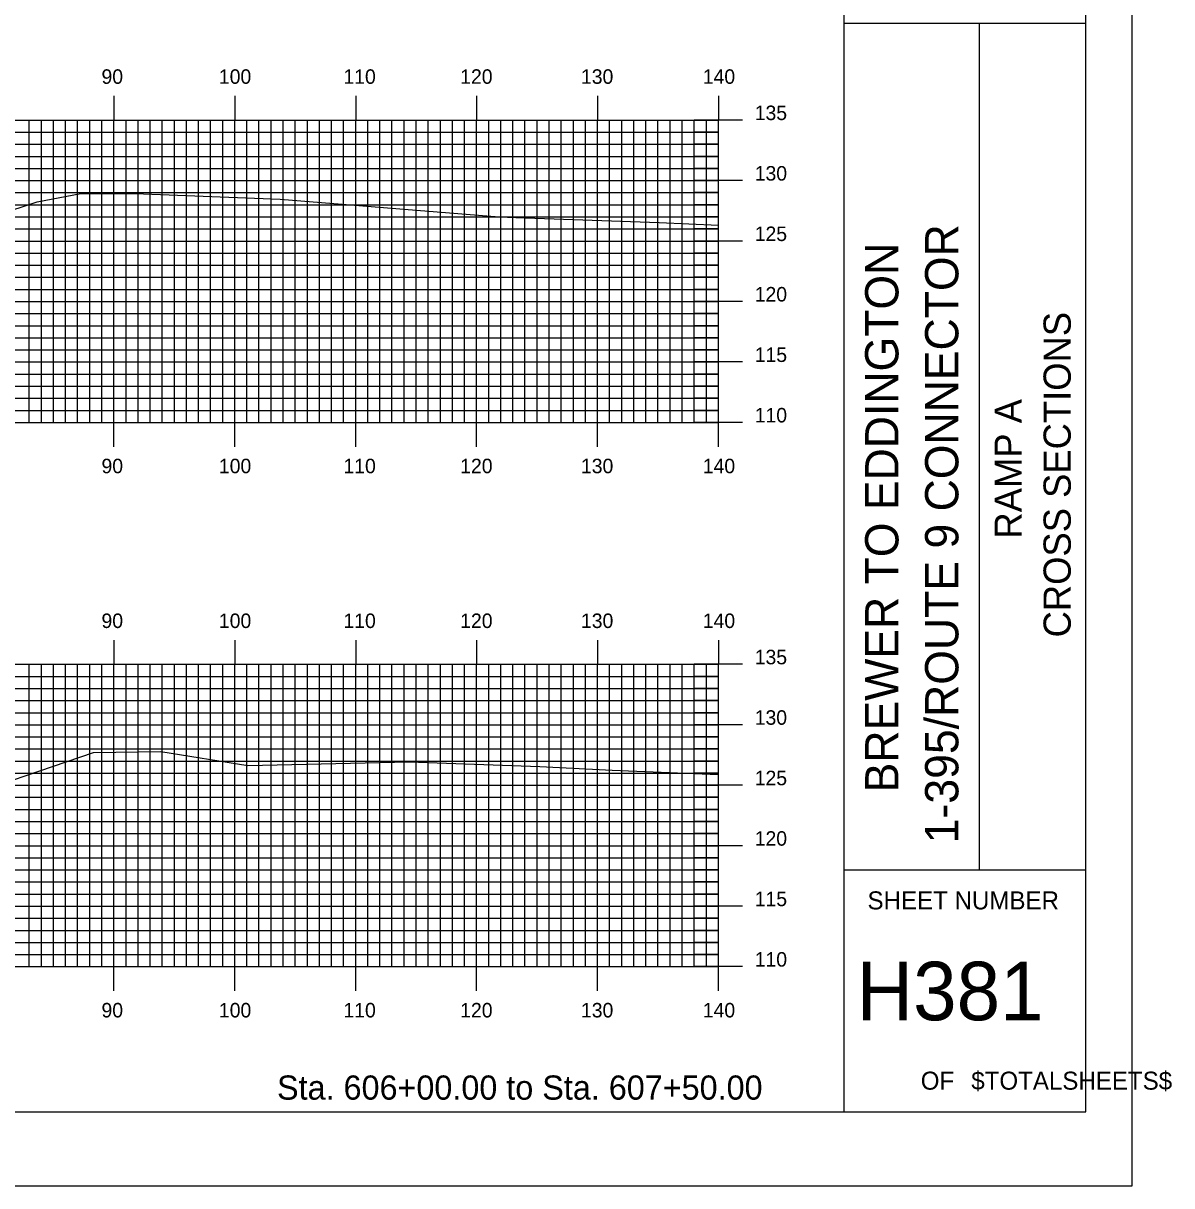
# Model space of a CAD drawing. Extents: x 842569 to 842912, y 363538 to 363758.
# Drawn here: x 842816.9 to 842911.9, y 363537.6 to 363633.7 of the extents above; entities that cross this region are included whole.
import ezdxf

# ---------------------------------------------------------------- set-up
doc = ezdxf.new("R2010")
doc.units = 0
for name, color, linetype in [('BORDER', 7, 'Continuous'), ('H_V ANNOTATION', 7, 'Continuous'), ('MAJOR', 7, 'Continuous'), ('MINOR', 7, 'Continuous'), ('PLOT BOUNDARY', 7, 'Continuous'), ('S_Roadway_Centerline', 7, 'Continuous')]:
    doc.layers.add(name, color=color, linetype=linetype)

msp = doc.modelspace()

# ---------------------------------------------------------------- linework, layer by layer
at = {"layer": 'BORDER'}
for p, q in [((842884.798, 363543.721), (842884.798, 363753.721)), ((842884.798, 363633.727), (842904.798, 363633.727)), ((842895.98, 363563.727), (842895.98, 363633.727)), ((842884.798, 363563.727), (842904.798, 363563.727))]:
    msp.add_line(p, q, dxfattribs=at)
msp.add_lwpolyline([(842584.798, 363543.721), (842904.798, 363543.721), (842904.798, 363753.721), (842584.798, 363753.721)], close=True, dxfattribs=at)
at = {"layer": 'MAJOR'}
for p, q in [((842824.398, 363627.725), (842824.398, 363625.721)), ((842834.398, 363627.725), (842834.398, 363625.721)), ((842844.398, 363627.725), (842844.398, 363625.721)), ((842854.398, 363627.725), (842854.398, 363625.721)), ((842864.398, 363627.725), (842864.398, 363625.721)), ((842874.398, 363627.725), (842874.398, 363625.721)), ((842594.398, 363625.721), (842874.398, 363625.721)), ((842594.398, 363625.721), (842874.398, 363625.721)), ((842824.398, 363600.721), (842824.398, 363625.721)), ((842834.398, 363600.721), (842834.398, 363625.721)), ((842844.398, 363600.721), (842844.398, 363625.721)), ((842854.398, 363600.721), (842854.398, 363625.721)), ((842864.398, 363600.721), (842864.398, 363625.721)), ((842876.402, 363625.721), (842872.394, 363625.721)), ((842874.398, 363600.721), (842874.398, 363625.721)), ((842874.398, 363600.721), (842874.398, 363625.721)), ((842594.398, 363620.721), (842874.398, 363620.721)), ((842876.402, 363620.721), (842872.394, 363620.721)), ((842594.398, 363615.721), (842874.398, 363615.721)), ((842876.402, 363615.721), (842872.394, 363615.721)), ((842594.398, 363610.721), (842874.398, 363610.721)), ((842876.402, 363610.721), (842872.394, 363610.721)), ((842594.398, 363605.721), (842874.398, 363605.721)), ((842876.402, 363605.721), (842872.394, 363605.721)), ((842594.398, 363600.721), (842874.398, 363600.721)), ((842594.398, 363600.721), (842874.398, 363600.721)), ((842824.398, 363598.717), (842824.398, 363600.721)), ((842834.398, 363598.717), (842834.398, 363600.721)), ((842844.398, 363598.717), (842844.398, 363600.721)), ((842854.398, 363598.717), (842854.398, 363600.721)), ((842864.398, 363598.717), (842864.398, 363600.721)), ((842876.402, 363600.721), (842872.394, 363600.721)), ((842874.398, 363598.717), (842874.398, 363600.721)), ((842824.398, 363582.725), (842824.398, 363580.721)), ((842834.398, 363582.725), (842834.398, 363580.721)), ((842844.398, 363582.725), (842844.398, 363580.721)), ((842854.398, 363582.725), (842854.398, 363580.721)), ((842864.398, 363582.725), (842864.398, 363580.721)), ((842874.398, 363582.725), (842874.398, 363580.721)), ((842594.398, 363580.721), (842874.398, 363580.721)), ((842594.398, 363580.721), (842874.398, 363580.721)), ((842824.398, 363555.721), (842824.398, 363580.721)), ((842834.398, 363555.721), (842834.398, 363580.721)), ((842844.398, 363555.721), (842844.398, 363580.721)), ((842854.398, 363555.721), (842854.398, 363580.721)), ((842864.398, 363555.721), (842864.398, 363580.721)), ((842876.402, 363580.721), (842872.394, 363580.721)), ((842874.398, 363555.721), (842874.398, 363580.721)), ((842874.398, 363555.721), (842874.398, 363580.721)), ((842594.398, 363575.721), (842874.398, 363575.721)), ((842876.402, 363575.721), (842872.394, 363575.721)), ((842594.398, 363570.721), (842874.398, 363570.721)), ((842876.402, 363570.721), (842872.394, 363570.721)), ((842594.398, 363565.721), (842874.398, 363565.721)), ((842876.402, 363565.721), (842872.394, 363565.721)), ((842594.398, 363560.721), (842874.398, 363560.721)), ((842876.402, 363560.721), (842872.394, 363560.721)), ((842594.398, 363555.721), (842874.398, 363555.721)), ((842594.398, 363555.721), (842874.398, 363555.721)), ((842824.398, 363553.717), (842824.398, 363555.721)), ((842834.398, 363553.717), (842834.398, 363555.721)), ((842844.398, 363553.717), (842844.398, 363555.721)), ((842854.398, 363553.717), (842854.398, 363555.721)), ((842864.398, 363553.717), (842864.398, 363555.721)), ((842876.402, 363555.721), (842872.394, 363555.721)), ((842874.398, 363553.717), (842874.398, 363555.721))]:
    msp.add_line(p, q, dxfattribs=at)
at = {"layer": 'MINOR'}
for p, q in [((842817.398, 363600.721), (842817.398, 363625.721)), ((842818.398, 363600.721), (842818.398, 363625.721)), ((842819.398, 363600.721), (842819.398, 363625.721)), ((842820.398, 363600.721), (842820.398, 363625.721)), ((842821.398, 363600.721), (842821.398, 363625.721)), ((842822.398, 363600.721), (842822.398, 363625.721)), ((842823.398, 363600.721), (842823.398, 363625.721)), ((842825.398, 363600.721), (842825.398, 363625.721)), ((842826.398, 363600.721), (842826.398, 363625.721)), ((842827.398, 363600.721), (842827.398, 363625.721)), ((842828.398, 363600.721), (842828.398, 363625.721)), ((842829.398, 363600.721), (842829.398, 363625.721)), ((842830.398, 363600.721), (842830.398, 363625.721)), ((842831.398, 363600.721), (842831.398, 363625.721)), ((842832.398, 363600.721), (842832.398, 363625.721)), ((842833.398, 363600.721), (842833.398, 363625.721)), ((842835.398, 363600.721), (842835.398, 363625.721)), ((842836.398, 363600.721), (842836.398, 363625.721)), ((842837.398, 363600.721), (842837.398, 363625.721)), ((842838.398, 363600.721), (842838.398, 363625.721)), ((842839.398, 363600.721), (842839.398, 363625.721)), ((842840.398, 363600.721), (842840.398, 363625.721)), ((842841.398, 363600.721), (842841.398, 363625.721)), ((842842.398, 363600.721), (842842.398, 363625.721)), ((842843.398, 363600.721), (842843.398, 363625.721)), ((842845.398, 363600.721), (842845.398, 363625.721)), ((842846.398, 363600.721), (842846.398, 363625.721)), ((842847.398, 363600.721), (842847.398, 363625.721)), ((842848.398, 363600.721), (842848.398, 363625.721)), ((842849.398, 363600.721), (842849.398, 363625.721)), ((842850.398, 363600.721), (842850.398, 363625.721)), ((842851.398, 363600.721), (842851.398, 363625.721)), ((842852.398, 363600.721), (842852.398, 363625.721)), ((842853.398, 363600.721), (842853.398, 363625.721)), ((842855.398, 363600.721), (842855.398, 363625.721)), ((842856.398, 363600.721), (842856.398, 363625.721)), ((842857.398, 363600.721), (842857.398, 363625.721)), ((842858.398, 363600.721), (842858.398, 363625.721)), ((842859.398, 363600.721), (842859.398, 363625.721)), ((842860.398, 363600.721), (842860.398, 363625.721)), ((842861.398, 363600.721), (842861.398, 363625.721)), ((842862.398, 363600.721), (842862.398, 363625.721)), ((842863.398, 363600.721), (842863.398, 363625.721)), ((842865.398, 363600.721), (842865.398, 363625.721)), ((842866.398, 363600.721), (842866.398, 363625.721)), ((842867.398, 363600.721), (842867.398, 363625.721)), ((842868.398, 363600.721), (842868.398, 363625.721)), ((842869.398, 363600.721), (842869.398, 363625.721)), ((842870.398, 363600.721), (842870.398, 363625.721)), ((842871.398, 363600.721), (842871.398, 363625.721)), ((842872.398, 363600.721), (842872.398, 363625.721)), ((842873.398, 363600.721), (842873.398, 363625.721)), ((842594.398, 363624.721), (842874.398, 363624.721)), ((842874.398, 363624.721), (842872.394, 363624.721)), ((842594.398, 363623.721), (842874.398, 363623.721)), ((842874.398, 363623.721), (842872.394, 363623.721)), ((842594.398, 363622.721), (842874.398, 363622.721)), ((842874.398, 363622.721), (842872.394, 363622.721)), ((842594.398, 363621.721), (842874.398, 363621.721)), ((842874.398, 363621.721), (842872.394, 363621.721)), ((842594.398, 363619.721), (842874.398, 363619.721)), ((842874.398, 363619.721), (842872.394, 363619.721)), ((842594.398, 363618.721), (842874.398, 363618.721)), ((842874.398, 363618.721), (842872.394, 363618.721)), ((842594.398, 363617.721), (842874.398, 363617.721)), ((842874.398, 363617.721), (842872.394, 363617.721)), ((842594.398, 363616.721), (842874.398, 363616.721)), ((842874.398, 363616.721), (842872.394, 363616.721)), ((842594.398, 363614.721), (842874.398, 363614.721)), ((842874.398, 363614.721), (842872.394, 363614.721)), ((842594.398, 363613.721), (842874.398, 363613.721)), ((842874.398, 363613.721), (842872.394, 363613.721)), ((842594.398, 363612.721), (842874.398, 363612.721)), ((842874.398, 363612.721), (842872.394, 363612.721)), ((842594.398, 363611.721), (842874.398, 363611.721)), ((842874.398, 363611.721), (842872.394, 363611.721)), ((842594.398, 363609.721), (842874.398, 363609.721)), ((842874.398, 363609.721), (842872.394, 363609.721)), ((842594.398, 363608.721), (842874.398, 363608.721)), ((842874.398, 363608.721), (842872.394, 363608.721)), ((842594.398, 363607.721), (842874.398, 363607.721)), ((842874.398, 363607.721), (842872.394, 363607.721)), ((842594.398, 363606.721), (842874.398, 363606.721)), ((842874.398, 363606.721), (842872.394, 363606.721)), ((842594.398, 363604.721), (842874.398, 363604.721)), ((842874.398, 363604.721), (842872.394, 363604.721)), ((842594.398, 363603.721), (842874.398, 363603.721)), ((842874.398, 363603.721), (842872.394, 363603.721)), ((842594.398, 363602.721), (842874.398, 363602.721)), ((842874.398, 363602.721), (842872.394, 363602.721)), ((842594.398, 363601.721), (842874.398, 363601.721)), ((842874.398, 363601.721), (842872.394, 363601.721)), ((842817.398, 363555.721), (842817.398, 363580.721)), ((842818.398, 363555.721), (842818.398, 363580.721)), ((842819.398, 363555.721), (842819.398, 363580.721)), ((842820.398, 363555.721), (842820.398, 363580.721)), ((842821.398, 363555.721), (842821.398, 363580.721)), ((842822.398, 363555.721), (842822.398, 363580.721)), ((842823.398, 363555.721), (842823.398, 363580.721)), ((842825.398, 363555.721), (842825.398, 363580.721)), ((842826.398, 363555.721), (842826.398, 363580.721)), ((842827.398, 363555.721), (842827.398, 363580.721)), ((842828.398, 363555.721), (842828.398, 363580.721)), ((842829.398, 363555.721), (842829.398, 363580.721)), ((842830.398, 363555.721), (842830.398, 363580.721)), ((842831.398, 363555.721), (842831.398, 363580.721)), ((842832.398, 363555.721), (842832.398, 363580.721)), ((842833.398, 363555.721), (842833.398, 363580.721)), ((842835.398, 363555.721), (842835.398, 363580.721)), ((842836.398, 363555.721), (842836.398, 363580.721)), ((842837.398, 363555.721), (842837.398, 363580.721)), ((842838.398, 363555.721), (842838.398, 363580.721)), ((842839.398, 363555.721), (842839.398, 363580.721)), ((842840.398, 363555.721), (842840.398, 363580.721)), ((842841.398, 363555.721), (842841.398, 363580.721)), ((842842.398, 363555.721), (842842.398, 363580.721)), ((842843.398, 363555.721), (842843.398, 363580.721)), ((842845.398, 363555.721), (842845.398, 363580.721)), ((842846.398, 363555.721), (842846.398, 363580.721)), ((842847.398, 363555.721), (842847.398, 363580.721)), ((842848.398, 363555.721), (842848.398, 363580.721)), ((842849.398, 363555.721), (842849.398, 363580.721)), ((842850.398, 363555.721), (842850.398, 363580.721)), ((842851.398, 363555.721), (842851.398, 363580.721)), ((842852.398, 363555.721), (842852.398, 363580.721)), ((842853.398, 363555.721), (842853.398, 363580.721)), ((842855.398, 363555.721), (842855.398, 363580.721)), ((842856.398, 363555.721), (842856.398, 363580.721)), ((842857.398, 363555.721), (842857.398, 363580.721)), ((842858.398, 363555.721), (842858.398, 363580.721)), ((842859.398, 363555.721), (842859.398, 363580.721)), ((842860.398, 363555.721), (842860.398, 363580.721)), ((842861.398, 363555.721), (842861.398, 363580.721)), ((842862.398, 363555.721), (842862.398, 363580.721)), ((842863.398, 363555.721), (842863.398, 363580.721)), ((842865.398, 363555.721), (842865.398, 363580.721)), ((842866.398, 363555.721), (842866.398, 363580.721)), ((842867.398, 363555.721), (842867.398, 363580.721)), ((842868.398, 363555.721), (842868.398, 363580.721)), ((842869.398, 363555.721), (842869.398, 363580.721)), ((842870.398, 363555.721), (842870.398, 363580.721)), ((842871.398, 363555.721), (842871.398, 363580.721)), ((842872.398, 363555.721), (842872.398, 363580.721)), ((842873.398, 363555.721), (842873.398, 363580.721)), ((842594.398, 363579.721), (842874.398, 363579.721)), ((842874.398, 363579.721), (842872.394, 363579.721)), ((842594.398, 363578.721), (842874.398, 363578.721)), ((842874.398, 363578.721), (842872.394, 363578.721)), ((842594.398, 363577.721), (842874.398, 363577.721)), ((842874.398, 363577.721), (842872.394, 363577.721)), ((842594.398, 363576.721), (842874.398, 363576.721)), ((842874.398, 363576.721), (842872.394, 363576.721)), ((842594.398, 363574.721), (842874.398, 363574.721)), ((842874.398, 363574.721), (842872.394, 363574.721)), ((842594.398, 363573.721), (842874.398, 363573.721)), ((842874.398, 363573.721), (842872.394, 363573.721)), ((842594.398, 363572.721), (842874.398, 363572.721)), ((842874.398, 363572.721), (842872.394, 363572.721)), ((842594.398, 363571.721), (842874.398, 363571.721)), ((842874.398, 363571.721), (842872.394, 363571.721)), ((842594.398, 363569.721), (842874.398, 363569.721)), ((842874.398, 363569.721), (842872.394, 363569.721)), ((842594.398, 363568.721), (842874.398, 363568.721)), ((842874.398, 363568.721), (842872.394, 363568.721)), ((842594.398, 363567.721), (842874.398, 363567.721)), ((842874.398, 363567.721), (842872.394, 363567.721)), ((842594.398, 363566.721), (842874.398, 363566.721)), ((842874.398, 363566.721), (842872.394, 363566.721)), ((842594.398, 363564.721), (842874.398, 363564.721)), ((842874.398, 363564.721), (842872.394, 363564.721)), ((842594.398, 363563.721), (842874.398, 363563.721)), ((842874.398, 363563.721), (842872.394, 363563.721)), ((842594.398, 363562.721), (842874.398, 363562.721)), ((842874.398, 363562.721), (842872.394, 363562.721)), ((842594.398, 363561.721), (842874.398, 363561.721)), ((842874.398, 363561.721), (842872.394, 363561.721)), ((842594.398, 363559.721), (842874.398, 363559.721)), ((842874.398, 363559.721), (842872.394, 363559.721)), ((842594.398, 363558.721), (842874.398, 363558.721)), ((842874.398, 363558.721), (842872.394, 363558.721)), ((842594.398, 363557.721), (842874.398, 363557.721)), ((842874.398, 363557.721), (842872.394, 363557.721)), ((842594.398, 363556.721), (842874.398, 363556.721)), ((842874.398, 363556.721), (842872.394, 363556.721))]:
    msp.add_line(p, q, dxfattribs=at)
at = {"layer": 'PLOT BOUNDARY'}
msp.add_lwpolyline([(842568.611, 363537.603), (842908.611, 363537.603), (842908.611, 363757.603), (842568.611, 363757.603)], close=True, dxfattribs=at)
at = {"layer": 'S_Roadway_Centerline'}
for points in [[(842808.109, 363615.69), (842818.05, 363618.967), (842821.663, 363619.658), (842826.139, 363619.652), (842838.152, 363619.176), (842856.255, 363617.711), (842857.64, 363617.662), (842869.502, 363617.248), (842874.398, 363617.047)], [(842714.747, 363572.471), (842722.633, 363572.897), (842726.809, 363573.013), (842732.419, 363573.194), (842735.014, 363573.088), (842742.618, 363573.139), (842742.909, 363573.078), (842750.574, 363572.134), (842751.687, 363571.983), (842763.388, 363570.175), (842771.512, 363568.763), (842784.256, 363566.248), (842790.297, 363565.206), (842795.137, 363564.57), (842796.81, 363565.629), (842810.416, 363569.237), (842822.719, 363573.436), (842828.267, 363573.503), (842835.487, 363572.347), (842848.826, 363572.658), (842859.64, 363572.272), (842865.612, 363571.957), (842874.398, 363571.619)]]:
    msp.add_lwpolyline(points, dxfattribs=at)

# ---------------------------------------------------------------- texts
at = {"layer": 'BORDER'}
for s, height, p in [('1-395/ROUTE 9 CONNECTOR', 2.75575, (842894.247, 363565.921)), ('BREWER TO EDDINGTON', 2.75575, (842889.287, 363570.13)), ('CROSS SECTIONS', 2.25, (842903.539, 363582.943)), ('RAMP A', 2.25, (842899.489, 363591.118))]:
    msp.add_text(s, height=height, rotation=90, dxfattribs=at).set_placement(p)
for s, height, p in [('SHEET NUMBER', 1.49054, (842886.729, 363560.454)), ('H381', 4.8388, (842885.829, 363551.286)), ('OF', 1.4905, (842891.132, 363545.547)), ('$TOTALSHEETS$', 1.49054, (842895.311, 363545.547))]:
    msp.add_text(s, height=height, dxfattribs=at).set_placement(p)
at = {"layer": 'H_V ANNOTATION'}
for s, height, p in [('90', 1.2, (842823.37, 363628.721)), ('100', 1.2, (842833.081, 363628.721)), ('110', 1.2, (842843.381, 363628.721)), ('120', 1.2, (842853.039, 363628.721)), ('130', 1.2, (842863.028, 363628.721)), ('140', 1.2, (842873.103, 363628.721)), ('135', 1.2, (842877.398, 363625.721)), ('130', 1.2, (842877.398, 363620.721)), ('125', 1.2, (842877.398, 363615.721)), ('120', 1.2, (842877.398, 363610.721)), ('115', 1.2, (842877.398, 363605.721)), ('110', 1.2, (842877.398, 363600.721)), ('90', 1.2, (842823.37, 363596.521)), ('100', 1.2, (842833.081, 363596.521)), ('110', 1.2, (842843.381, 363596.521)), ('120', 1.2, (842853.039, 363596.521)), ('130', 1.2, (842863.028, 363596.521)), ('140', 1.2, (842873.103, 363596.521)), ('90', 1.2, (842823.37, 363583.721)), ('100', 1.2, (842833.081, 363583.721)), ('110', 1.2, (842843.381, 363583.721)), ('120', 1.2, (842853.039, 363583.721)), ('130', 1.2, (842863.028, 363583.721)), ('140', 1.2, (842873.103, 363583.721)), ('135', 1.2, (842877.398, 363580.721)), ('130', 1.2, (842877.398, 363575.721)), ('125', 1.2, (842877.398, 363570.721)), ('120', 1.2, (842877.398, 363565.721)), ('115', 1.2, (842877.398, 363560.721)), ('110', 1.2, (842877.398, 363555.721)), ('90', 1.2, (842823.37, 363551.521)), ('100', 1.2, (842833.081, 363551.521)), ('110', 1.2, (842843.381, 363551.521)), ('120', 1.2, (842853.039, 363551.521)), ('130', 1.2, (842863.028, 363551.521)), ('140', 1.2, (842873.103, 363551.521)), ('Sta. 606+00.00 to Sta. 607+50.00', 2.0004, (842837.89, 363544.721))]:
    msp.add_text(s, height=height, dxfattribs=at).set_placement(p)

doc.saveas('drawing.dxf')
